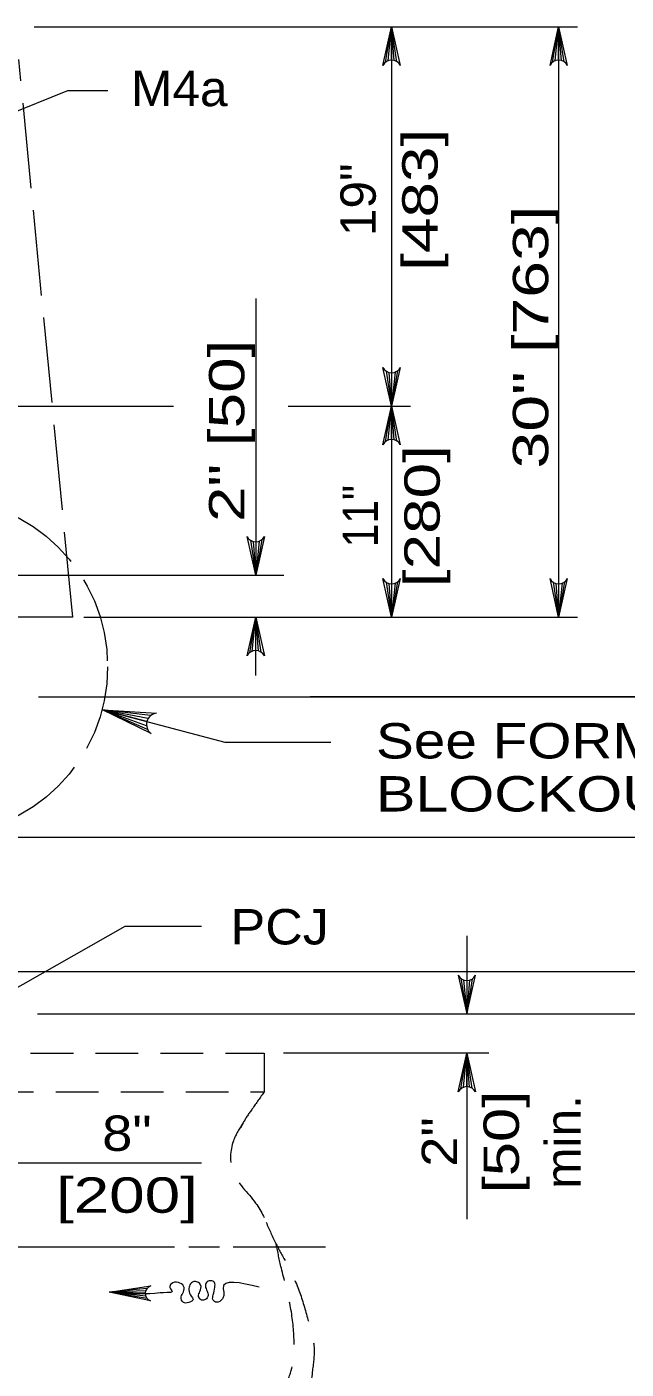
# Model space of a CAD drawing. Extents: x -1431.2 to -1397.2, y -1045.1 to -1001.1.
# Drawn here: x -1420.61 to -1417.92, y -1041.7 to -1035.67 of the extents above; entities that cross this region are included whole.
import ezdxf
from ezdxf.enums import TextEntityAlignment as Align

# ---------------------------------------------------------------- set-up
doc = ezdxf.new("R2010")
doc.units = 0
doc.header["$LTSCALE"] = 0.064
doc.linetypes.add('LONG_DASHED', pattern=[7.5, 6, -1.5])
doc.linetypes.add('MEDIUM_DASHED', pattern=[4.5, 3, -1.5])
doc.layers.add('1', color=7, linetype='Continuous', lineweight=13)

msp = doc.modelspace()

# ---------------------------------------------------------------- linework, layer by layer
at = {"layer": '1'}
for p, q in [((-1420.57742, -1035.6715), (-1418.13558, -1035.6715)), ((-1418.99833, -1035.83025), (-1418.97133, -1035.6715)), ((-1418.987, -1035.82425), (-1418.97133, -1035.6715)), ((-1418.97133, -1035.6715), (-1418.97133, -1038.32275)), ((-1418.97133, -1035.82142), (-1418.97133, -1035.6715)), ((-1418.959, -1035.82308), (-1418.97133, -1035.6715)), ((-1418.947, -1035.82842), (-1418.97133, -1035.6715)), ((-1418.24758, -1035.83025), (-1418.22058, -1035.6715)), ((-1418.23625, -1035.82425), (-1418.22058, -1035.6715)), ((-1418.22058, -1035.82142), (-1418.22058, -1035.6715)), ((-1418.20825, -1035.82308), (-1418.22058, -1035.6715)), ((-1418.19617, -1035.82842), (-1418.22058, -1035.6715)), ((-1419.58142, -1036.89167), (-1419.58142, -1038.13367)), ((-1418.99575, -1037.21783), (-1418.97133, -1037.37467)), ((-1418.98367, -1037.22308), (-1418.97133, -1037.37467)), ((-1418.94442, -1037.21592), (-1418.97133, -1037.37467)), ((-1418.95567, -1037.22192), (-1418.97133, -1037.37467)), ((-1418.97133, -1037.22475), (-1418.97133, -1037.37467)), ((-1421.806, -1037.37467), (-1419.95125, -1037.37467)), ((-1419.43608, -1037.37467), (-1418.88633, -1037.37467)), ((-1418.99833, -1037.53342), (-1418.97133, -1037.37467)), ((-1418.987, -1037.52742), (-1418.97133, -1037.37467)), ((-1418.97133, -1037.52467), (-1418.97133, -1037.37467)), ((-1418.959, -1037.52625), (-1418.97133, -1037.37467)), ((-1418.947, -1037.53158), (-1418.97133, -1037.37467)), ((-1419.60583, -1037.97675), (-1419.58142, -1038.13367)), ((-1419.59375, -1037.98208), (-1419.58142, -1038.13367)), ((-1419.55442, -1037.97492), (-1419.58142, -1038.13367)), ((-1419.56575, -1037.98092), (-1419.58142, -1038.13367)), ((-1419.58142, -1037.98367), (-1419.58142, -1038.13367)), ((-1420.90908, -1038.13367), (-1419.45592, -1038.13367)), ((-1418.99575, -1038.16583), (-1418.97133, -1038.32275)), ((-1418.98367, -1038.17117), (-1418.97133, -1038.32275)), ((-1418.94442, -1038.164), (-1418.97133, -1038.32275)), ((-1418.95567, -1038.17), (-1418.97133, -1038.32275)), ((-1418.97133, -1038.17283), (-1418.97133, -1038.32275)), ((-1418.245, -1038.16583), (-1418.22058, -1038.32275)), ((-1418.23292, -1038.17117), (-1418.22058, -1038.32275)), ((-1418.19367, -1038.164), (-1418.22058, -1038.32275)), ((-1418.20492, -1038.17), (-1418.22058, -1038.32275)), ((-1418.22058, -1038.17283), (-1418.22058, -1038.32275)), ((-1420.35475, -1038.32275), (-1418.13558, -1038.32275)), ((-1419.60833, -1038.4815), (-1419.58142, -1038.32275)), ((-1419.59708, -1038.4755), (-1419.58142, -1038.32275)), ((-1419.58142, -1038.47275), (-1419.58142, -1038.32275)), ((-1419.56908, -1038.47433), (-1419.58142, -1038.32275)), ((-1419.557, -1038.47967), (-1419.58142, -1038.32275)), ((-1419.58142, -1038.58433), (-1419.58142, -1038.32275)), ((-1420.55817, -1038.68067), (-1414.82, -1038.68067)), ((-1415.61583, -1038.68067), (-1419.337, -1038.68067)), ((-1420.07083, -1038.79117), (-1420.26975, -1038.73883)), ((-1420.07208, -1038.81083), (-1420.26975, -1038.73883)), ((-1420.06767, -1038.82642), (-1420.26975, -1038.73883)), ((-1420.06483, -1038.77708), (-1420.26975, -1038.73883)), ((-1420.054, -1038.7645), (-1420.26975, -1038.73883)), ((-1421.27142, -1039.31042), (-1415.55833, -1039.31042)), ((-1418.633, -1039.75292), (-1418.633, -1040.10125)), ((-1420.77192, -1039.91325), (-1415.55833, -1039.91325)), ((-1418.66, -1039.945), (-1418.633, -1040.10375)), ((-1418.64867, -1039.951), (-1418.633, -1040.10375)), ((-1418.60867, -1039.94683), (-1418.633, -1040.10375)), ((-1418.62075, -1039.95217), (-1418.633, -1040.10375)), ((-1418.633, -1039.95375), (-1418.633, -1040.10375)), ((-1420.562, -1040.10408), (-1414.82, -1040.10408)), ((-1420.477, -1040.10408), (-1419.167, -1040.10408)), ((-1418.633, -1040.10133), (-1418.633, -1040.10125)), ((-1418.53442, -1040.28092), (-1419.45708, -1040.28092)), ((-1418.66, -1040.43967), (-1418.633, -1040.28092)), ((-1418.64867, -1040.43367), (-1418.633, -1040.28092)), ((-1418.633, -1040.28092), (-1418.633, -1041.02625)), ((-1418.633, -1040.43083), (-1418.633, -1040.28092)), ((-1418.62075, -1040.4325), (-1418.633, -1040.28092)), ((-1418.60867, -1040.43775), (-1418.633, -1040.28092)), ((-1421.35642, -1040.773), (-1419.82525, -1040.773)), ((-1419.9465, -1041.15183), (-1420.649, -1041.15183)), ((-1419.74492, -1041.15183), (-1419.88292, -1041.15183)), ((-1419.26833, -1041.15183), (-1419.68358, -1041.15183)), ((-1420.07042, -1041.3375), (-1420.24033, -1041.35408)), ((-1420.07658, -1041.34792), (-1420.24033, -1041.35408)), ((-1420.07867, -1041.35867), (-1420.24033, -1041.35408)), ((-1420.07617, -1041.37242), (-1420.24033, -1041.35408)), ((-1420.07008, -1041.38242), (-1420.24033, -1041.35408))]:
    msp.add_line(p, q, dxfattribs=at)
at = {"layer": '1', "linetype": 'LONG_DASHED'}
for q in [(-1420.64592, -1035.81858), (-1420.649, -1038.32275)]:
    msp.add_line((-1420.40408, -1038.32275), q, dxfattribs=at)
at = {"layer": '1', "linetype": 'MEDIUM_DASHED'}
for p, q in [((-1420.59325, -1040.28092), (-1419.54317, -1040.28092)), ((-1419.54317, -1040.28092), (-1419.54317, -1040.45358)), ((-1421.35642, -1040.45358), (-1419.54317, -1040.45358))]:
    msp.add_line(p, q, dxfattribs=at)
at = {"layer": '1'}
for points in [[(-1419.00983, -1035.84475), (-1418.97133, -1035.6715), (-1418.93283, -1035.84475)], [(-1418.25908, -1035.84475), (-1418.22058, -1035.6715), (-1418.18208, -1035.84475)], [(-1418.22058, -1035.6715), (-1418.22058, -1035.98833), (-1418.22058, -1038.32275)], [(-1420.97642, -1036.1785), (-1420.42558, -1035.95792), (-1420.24558, -1035.95792)], [(-1418.93283, -1037.20142), (-1418.97133, -1037.37467), (-1419.00983, -1037.20142)], [(-1419.00983, -1037.548), (-1418.97133, -1037.37467), (-1418.93283, -1037.548)], [(-1419.54292, -1037.96033), (-1419.58142, -1038.13367), (-1419.61992, -1037.96033)], [(-1418.93283, -1038.1495), (-1418.97133, -1038.32275), (-1419.00983, -1038.1495)], [(-1418.18208, -1038.1495), (-1418.22058, -1038.32275), (-1418.25908, -1038.1495)], [(-1419.61992, -1038.49608), (-1419.58142, -1038.32275), (-1419.54292, -1038.49608)], [(-1420.26975, -1038.73883), (-1419.72025, -1038.88358), (-1419.2435, -1038.88358)], [(-1420.052, -1038.84533), (-1420.26975, -1038.73883), (-1420.02775, -1038.75342)], [(-1420.85742, -1040.10017), (-1420.16867, -1039.71008), (-1419.82525, -1039.71008)], [(-1418.67158, -1039.93042), (-1418.633, -1040.10375), (-1418.5945, -1039.93042)], [(-1418.67158, -1040.45417), (-1418.633, -1040.28092), (-1418.5945, -1040.45417)], [(-1420.05467, -1041.393), (-1420.24033, -1041.35408), (-1420.05242, -1041.32567)]]:
    msp.add_lwpolyline(points, dxfattribs=at)
at = {"layer": '1', "linetype": 'LONG_DASHED'}
msp.add_circle((-1421.00606, -1038.54482), 0.75881, dxfattribs=at)
at = {"layer": '1'}
msp.add_arc((-1420.02132, -1038.8042), 0.05131, 97.32819, 233.15432, dxfattribs=at)
for centre, major_axis, ratio, start_param, end_param in [((-1418.97132, -1035.85878), (0.04156, 0), 0.9, 0.3855052, 2.7561184), ((-1418.22054, -1035.85878), (0.04156, 0), 0.9, 0.3855052, 2.7561184), ((-1418.9714, -1037.18739), (-0.04156, 0), 0.9, 0.3855052, 2.7561184), ((-1418.97132, -1037.56199), (0.04156, 0), 0.9, 0.3855052, 2.7561184), ((-1419.58144, -1037.94635), (-0.04156, 0), 0.9, 0.3855052, 2.7561184), ((-1418.9714, -1038.13546), (-0.04156, 0), 0.9, 0.3855052, 2.7561184), ((-1418.22063, -1038.13546), (-0.04156, 0), 0.9, 0.3855052, 2.7561184), ((-1419.58136, -1038.51007), (0.04156, 0), 0.9, 0.3855052, 2.7561184), ((-1418.633, -1039.91644), (0.04156, 0), 0.9, 3.5270669, 5.8976801), ((-1418.633, -1040.46819), (0.04156, 0), 0.9, 0.3855052, 2.7561184), ((-1420.03838, -1041.35976), (-0.04034, 0), 0.899905, 5.0665441, 7.4371572)]:
    msp.add_ellipse(centre, major_axis=major_axis, ratio=ratio, start_param=start_param, end_param=end_param, dxfattribs=at)
at = {"layer": '1', "linetype": 'MEDIUM_DASHED'}
for points in [[(-1419.54317, -1040.45358), (-1419.59708, -1040.53033), (-1419.63825, -1040.59358), (-1419.64908, -1040.6155)], [(-1419.63775, -1040.59267), (-1419.6815, -1040.67375), (-1419.68475, -1040.81208), (-1419.58208, -1040.95342), (-1419.5185, -1041.07542)], [(-1419.53508, -1041.04), (-1419.48983, -1041.13783), (-1419.44392, -1041.22325), (-1419.38625, -1041.34875), (-1419.34692, -1041.47742), (-1419.3195, -1041.60192), (-1419.32758, -1041.71258), (-1419.35508, -1041.86433), (-1419.43308, -1041.97492), (-1419.54317, -1042.024)], [(-1419.54317, -1041.81), (-1419.46683, -1041.78608), (-1419.42225, -1041.70508), (-1419.40975, -1041.55742), (-1419.4285, -1041.40358), (-1419.46658, -1041.24533), (-1419.48983, -1041.13783)]]:
    msp.add_spline(points, degree=3, dxfattribs=at)
at = {"layer": '1'}
msp.add_spline([(-1419.56642, -1041.33117), (-1419.72808, -1041.33933), (-1419.72492, -1041.36883), (-1419.73142, -1041.38358), (-1419.75733, -1041.39933), (-1419.7735, -1041.38975), (-1419.77233, -1041.36558), (-1419.76567, -1041.33192), (-1419.76667, -1041.31075), (-1419.785, -1041.30225), (-1419.80325, -1041.31067), (-1419.80775, -1041.3265), (-1419.80033, -1041.34867), (-1419.79608, -1041.36867), (-1419.808, -1041.38658), (-1419.82525, -1041.38967), (-1419.83808, -1041.37283), (-1419.83258, -1041.35075), (-1419.82917, -1041.32117), (-1419.84317, -1041.30858), (-1419.86042, -1041.30633), (-1419.87767, -1041.32108), (-1419.88208, -1041.34325), (-1419.87142, -1041.37175), (-1419.86292, -1041.38542), (-1419.88242, -1041.40017), (-1419.90608, -1041.40017), (-1419.91675, -1041.37475), (-1419.90692, -1041.35267), (-1419.90575, -1041.32633), (-1419.92933, -1041.3105), (-1419.96058, -1041.31575), (-1419.96725, -1041.33358), (-1419.95758, -1041.3515), (-1419.97917, -1041.35567), (-1420.03517, -1041.35983), (-1420.24033, -1041.35408)], degree=3, dxfattribs=at)

# ---------------------------------------------------------------- texts
for s, width, p in [('M4a', 1.05, (-1420.14192, -1036.02767)), ('See FORMED', 1.2, (-1419.04125, -1038.95708)), ('BLOCKOUT Detail', 1.25, (-1419.04125, -1039.19525)), ('PCJ', 1.1, (-1419.69483, -1039.79217))]:
    msp.add_text(s, height=0.1588, dxfattribs=dict(at, width=width)).set_placement(p)
for s, width, p in [('[483]', 1.35, (-1418.7645, -1036.44817)), ('19"', 1.05, (-1419.04233, -1036.44808)), ('30" [763]', 1.4, (-1418.26717, -1037.06496)), ('[280]', 1.35, (-1418.75492, -1037.86896)), ('11"', 0.9, (-1419.03283, -1037.86896)), ('[50]', 1.3, (-1418.39908, -1040.67942)), ('min.', 1.05, (-1418.12125, -1040.67942)), ('2"', 1.15, (-1418.67692, -1040.67942))]:
    msp.add_text(s, height=0.1588, rotation=90, dxfattribs=dict(at, width=width)).set_placement(p, align=Align.CENTER)
at = {"layer": '1', "width": 1.35}
msp.add_text('2" [50]', height=0.1588, rotation=90, dxfattribs=at).set_placement((-1419.63283, -1037.89533))
at = {"layer": '1'}
for s, width, p in [('8"', 1.15, (-1420.1605, -1040.71933)), ('[200]', 1.35, (-1420.1605, -1040.99717))]:
    msp.add_text(s, height=0.1588, dxfattribs=dict(at, width=width)).set_placement(p, align=Align.CENTER)

doc.saveas('drawing.dxf')
